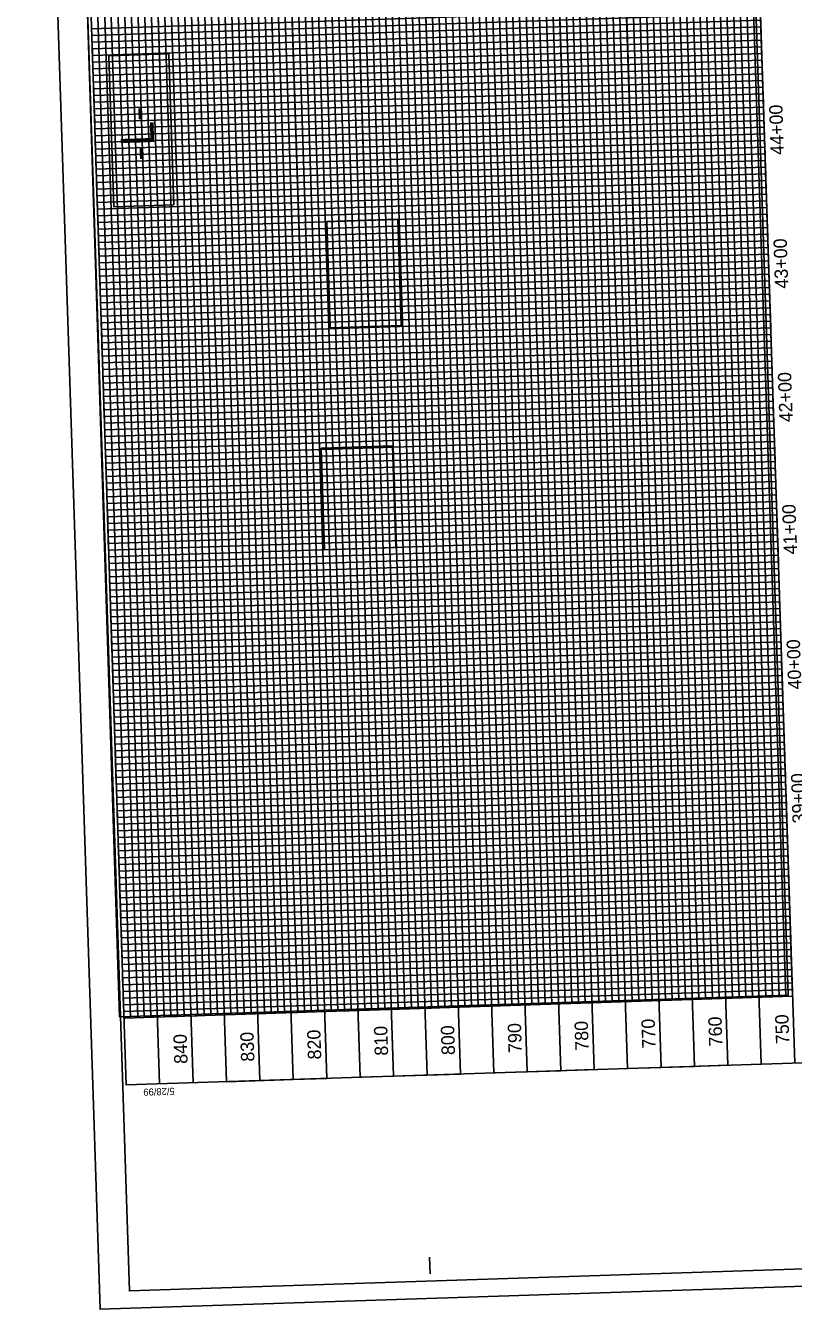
# Model space of a CAD drawing. Extents: x 1627318 to 1628473, y 762308 to 764226.
# Drawn here: x 1627318 to 1627891, y 762308 to 763268 of the extents above; entities that cross this region are included whole.
import ezdxf

# ---------------------------------------------------------------- set-up
doc = ezdxf.new("R2010")
doc.units = 0
for name, color, linetype in [('Exist Vertical Profile Horizontal Axis Label Major', 7, 'Continuous'), ('Exist Vertical Profile Vertical Axis Label', 7, 'Continuous'), ('Prop Grid Mask', 7, 'Continuous'), ('Sheet Data Field CELL', 7, 'Continuous'), ('Sheet DOT Grid CELL', 7, 'Continuous'), ('Sheet Layout Profile Border Port 1', 7, 'Continuous'), ('Sheet Plot Border Inside CELL', 7, 'Continuous'), ('Sheet Plot Border Outside CELL', 7, 'Continuous'), ('Sheet Profile CELL', 7, 'Continuous'), ('Sheet Profile Grid Major CELL', 7, 'Continuous'), ('Sheet Profile Grid Middle CELL', 7, 'Continuous'), ('Sheet Profile Grid Minor CELL', 7, 'Continuous')]:
    doc.layers.add(name, color=color, linetype=linetype)

msp = doc.modelspace()

# ---------------------------------------------------------------- linework, layer by layer
at = {"layer": 'Prop Grid Mask'}
for points in [[(1627428.21, 763133.99), (1627424.52, 763247.02), (1627379.8, 763245.55), (1627383.49, 763132.53)], [(1627545.26, 763042.21), (1627542.66, 763121.69), (1627595.71, 763123.43), (1627598.31, 763043.95)], [(1627540.99, 762876.11), (1627538.5, 762952.17), (1627591.68, 762953.91), (1627594.17, 762877.85)]]:
    msp.add_lwpolyline(points, close=True, dxfattribs=at)
at = {"layer": 'Sheet DOT Grid CELL'}
for p, q in [((1627593.48, 763983.54), (1627642.52, 762484.34)), ((1627643.46, 763985.17), (1627692.5, 762485.97)), ((1627693.43, 763986.81), (1627742.47, 762487.61)), ((1627743.4, 763988.44), (1627792.44, 762489.24)), ((1627793.38, 763990.08), (1627842.42, 762490.88)), ((1627500.08, 763780.37), (1627542.58, 762481.07)), ((1627550.05, 763781.96), (1627592.55, 762482.7)), ((1627400.13, 763777.06), (1627442.63, 762477.8)), ((1627450.11, 763778.69), (1627492.6, 762479.43)), ((1627867.87, 763242.11), (1627368.14, 763225.76)), ((1627869.51, 763192.14), (1627369.77, 763175.79)), ((1627871.14, 763142.16), (1627371.41, 763125.82)), ((1627872.77, 763092.19), (1627373.04, 763075.84)), ((1627874.41, 763042.22), (1627374.68, 763025.87)), ((1627876.04, 762992.24), (1627376.31, 762975.9)), ((1627877.68, 762942.27), (1627377.95, 762925.93)), ((1627879.31, 762892.3), (1627379.58, 762875.95)), ((1627880.95, 762842.32), (1627381.21, 762825.98)), ((1627882.58, 762792.35), (1627382.85, 762776.01)), ((1627884.22, 762742.38), (1627384.48, 762726.03)), ((1627885.85, 762692.4), (1627386.12, 762676.06)), ((1627887.49, 762642.43), (1627387.75, 762626.09)), ((1627889.12, 762592.46), (1627389.39, 762576.11)), ((1627890.76, 762542.49), (1627391.02, 762526.14))]:
    msp.add_line(p, q, dxfattribs=at)
at = {"layer": 'Sheet Layout Profile Border Port 1'}
msp.add_lwpolyline([(1627387.69, 762527.01), (1627887.42, 762543.36), (1627841.65, 763942.61), (1627566.8, 763933.62), (1627571.7, 763783.65), (1627346.82, 763776.3), (1627347.71, 763777.21)], close=True, dxfattribs=at)
msp.add_lwpolyline([(1627551.99, 762531.4), (1627890.76, 762542.49), (1627844.99, 763941.74), (1627570.13, 763932.75)], dxfattribs=at)
at = {"layer": 'Sheet Plot Border Inside CELL'}
msp.add_lwpolyline([(1628449.68, 762356.66), (1628395.2, 764022.27), (1627340.66, 763987.77), (1627395.14, 762322.16)], close=True, dxfattribs=at)
at = {"layer": 'Sheet Plot Border Outside CELL'}
msp.add_lwpolyline([(1628472.54, 762344.4), (1628416.96, 764043.49), (1627317.55, 764007.53), (1627373.13, 762308.44)], close=True, dxfattribs=at)
at = {"layer": 'Sheet Profile CELL'}
for p, q in [((1627892.39, 762492.51), (1627843.35, 763991.71)), ((1627619.89, 762335.02), (1627619.48, 762347.51))]:
    msp.add_line(p, q, dxfattribs=at)
msp.add_lwpolyline([(1627343.62, 763975.36), (1627392.66, 762476.17), (1628442.1, 762510.49), (1628393.06, 764009.69)], close=True, dxfattribs=at)
at = {"layer": 'Sheet Profile Grid Major CELL'}
for points in [[(1627550.05, 763782.01), (1627592.55, 762482.7), (1627642.52, 762484.34), (1627593.48, 763983.54)], [(1627643.46, 763985.17), (1627692.5, 762485.97), (1627742.47, 762487.61), (1627693.43, 763986.81)], [(1627743.4, 763988.44), (1627792.44, 762489.24), (1627792.44, 762489.24), (1627842.42, 762490.88), (1627793.38, 763990.08)], [(1627450.1, 763778.74), (1627492.6, 762479.43), (1627542.58, 762481.07), (1627500.08, 763780.37)], [(1627442.63, 762477.8), (1627400.13, 763777.11)], [(1627391.02, 762526.14), (1627890.76, 762542.49), (1627889.12, 762592.46), (1627389.39, 762576.11), (1627387.75, 762626.09), (1627887.49, 762642.43), (1627885.85, 762692.4), (1627386.12, 762676.06), (1627384.48, 762726.03), (1627884.22, 762742.38), (1627882.58, 762792.35), (1627382.85, 762776.01), (1627381.21, 762825.98), (1627880.95, 762842.32), (1627879.31, 762892.3), (1627379.58, 762875.95), (1627377.95, 762925.93), (1627877.68, 762942.27), (1627876.04, 762992.24), (1627376.31, 762975.9), (1627374.68, 763025.87), (1627874.41, 763042.22), (1627872.77, 763092.19), (1627373.04, 763075.84), (1627371.41, 763125.82), (1627871.14, 763142.16), (1627869.51, 763192.14), (1627369.77, 763175.79), (1627368.14, 763225.76), (1627867.87, 763242.11), (1627866.24, 763292.08)]]:
    msp.add_lwpolyline(points, dxfattribs=at)
at = {"layer": 'Sheet Profile Grid Middle CELL'}
msp.add_line((1627417.64, 762476.98), (1627375.15, 763776.24), dxfattribs=at)
for points in [[(1627818.36, 763990.89), (1627867.4, 762491.69)], [(1627618.47, 763984.35), (1627667.51, 762485.16), (1627717.48, 762486.79), (1627668.44, 763985.99)], [(1627718.42, 763987.62), (1627767.46, 762488.43), (1627817.43, 762490.06), (1627768.39, 763989.26)], [(1627525.07, 763781.14), (1627567.56, 762481.89), (1627617.54, 762483.52), (1627574.22, 763807.81)], [(1627425.12, 763777.92), (1627467.62, 762478.62), (1627517.59, 762480.25), (1627475.09, 763779.56)], [(1627390.21, 762551.13), (1627889.94, 762567.47), (1627888.3, 762617.44), (1627388.57, 762601.1), (1627386.94, 762651.07), (1627886.67, 762667.42), (1627885.03, 762717.39), (1627385.3, 762701.05), (1627383.67, 762751.02), (1627883.4, 762767.36), (1627881.76, 762817.34), (1627382.03, 762800.99), (1627380.4, 762850.97), (1627880.13, 762867.31), (1627878.5, 762917.28), (1627378.76, 762900.94), (1627377.13, 762950.91), (1627876.86, 762967.26), (1627875.23, 763017.23), (1627375.49, 763000.88), (1627373.86, 763050.86), (1627873.59, 763067.2), (1627871.96, 763117.18), (1627871.96, 763117.18), (1627372.22, 763100.83), (1627370.59, 763150.8), (1627870.32, 763167.15), (1627868.69, 763217.12), (1627368.96, 763200.78), (1627367.32, 763250.75), (1627867.05, 763267.1), (1627865.42, 763317.07)]]:
    msp.add_lwpolyline(points, dxfattribs=at)
at = {"layer": 'Sheet Profile Grid Minor CELL'}
for p, q in [((1627580.13, 763933.07), (1627625.9, 762533.82)), ((1627630.89, 762533.99), (1627585.12, 763933.24)), ((1627590.12, 763933.4), (1627635.89, 762534.15)), ((1627645.89, 762534.48), (1627600.12, 763933.73)), ((1627605.11, 763933.89), (1627650.88, 762534.64)), ((1627655.88, 762534.8), (1627610.11, 763934.05)), ((1627615.11, 763934.22), (1627660.88, 762534.97)), ((1627670.87, 762535.29), (1627625.1, 763934.54)), ((1627630.1, 763934.71), (1627675.87, 762535.46)), ((1627680.87, 762535.62), (1627635.1, 763934.87)), ((1627640.1, 763935.03), (1627685.86, 762535.78)), ((1627695.86, 762536.11), (1627650.09, 763935.36)), ((1627655.09, 763935.53), (1627700.86, 762536.27)), ((1627705.85, 762536.44), (1627660.08, 763935.69)), ((1627665.08, 763935.85), (1627710.85, 762536.6)), ((1627720.85, 762536.93), (1627675.08, 763936.18)), ((1627680.07, 763936.34), (1627725.84, 762537.09)), ((1627730.84, 762537.25), (1627685.07, 763936.51)), ((1627690.07, 763936.67), (1627735.84, 762537.42)), ((1627745.83, 762537.74), (1627700.06, 763937)), ((1627705.06, 763937.16), (1627750.83, 762537.91)), ((1627755.83, 762538.07), (1627710.06, 763937.32)), ((1627715.06, 763937.49), (1627760.82, 762538.24)), ((1627770.82, 762538.56), (1627725.05, 763937.81)), ((1627730.05, 763937.98), (1627775.82, 762538.73)), ((1627735.04, 763938.14), (1627780.81, 762538.89)), ((1627740.04, 763938.3), (1627785.81, 762539.05)), ((1627795.81, 762539.38), (1627750.04, 763938.63)), ((1627755.03, 763938.79), (1627800.8, 762539.54)), ((1627805.8, 762539.71), (1627760.03, 763938.96)), ((1627765.03, 763939.12), (1627810.8, 762539.87)), ((1627820.79, 762540.2), (1627775.02, 763939.45)), ((1627780.02, 763939.61), (1627825.79, 762540.36)), ((1627830.79, 762540.52), (1627785.02, 763939.78)), ((1627790.02, 763939.94), (1627835.78, 762540.69)), ((1627845.78, 762541.01), (1627800.01, 763940.27)), ((1627805.01, 763940.43), (1627850.78, 762541.18)), ((1627855.77, 762541.34), (1627810, 763940.59)), ((1627815, 763940.76), (1627860.77, 762541.5)), ((1627870.77, 762541.83), (1627825, 763941.08)), ((1627829.99, 763941.25), (1627875.76, 762541.99)), ((1627880.76, 762542.16), (1627834.99, 763941.41)), ((1627485.09, 763779.83), (1627525.95, 762530.55)), ((1627490.08, 763780.05), (1627530.95, 762530.72)), ((1627495.08, 763780.21), (1627535.94, 762530.88)), ((1627545.94, 762531.21), (1627505.07, 763780.54)), ((1627510.07, 763780.7), (1627550.94, 762531.37)), ((1627555.93, 762531.53), (1627515.07, 763780.81)), ((1627535.06, 763781.47), (1627575.92, 762532.19)), ((1627580.92, 762532.35), (1627540.06, 763781.63)), ((1627560.05, 763782.29), (1627600.91, 762533)), ((1627605.91, 762533.17), (1627565.04, 763782.45)), ((1627396.02, 762526.3), (1627355.15, 763775.63)), ((1627360.15, 763775.8), (1627401.37, 762526.48)), ((1627406.01, 762526.63), (1627365.15, 763775.96)), ((1627401.02, 762526.47), (1627401.02, 762526.47))]:
    msp.add_line(p, q, dxfattribs=at)
for points in [[(1627570.04, 763782.61), (1627610.9, 762533.33), (1627620.9, 762533.66), (1627575.13, 763932.91)], [(1627839.99, 763941.57), (1627885.76, 762542.32)], [(1627460.2, 763779.07), (1627501.06, 762529.84), (1627505.96, 762530), (1627465.1, 763779.23)], [(1627470.09, 763779.39), (1627510.96, 762530.06), (1627520.95, 762530.39), (1627480.09, 763779.72)], [(1627520.07, 763780.98), (1627560.93, 762531.7), (1627570.93, 762532.02), (1627530.06, 763781.31)], [(1627545.05, 763781.8), (1627585.92, 762532.51), (1627595.91, 762532.84), (1627555.05, 763782.12)], [(1627370.15, 763776.12), (1627411.01, 762526.79), (1627421.01, 762527.12), (1627380.14, 763776.45)], [(1627385.14, 763776.56), (1627426, 762527.28), (1627431, 762527.45), (1627390.14, 763776.78)], [(1627395.13, 763776.94), (1627436, 762527.61), (1627445.99, 762527.94), (1627405.13, 763777.27)], [(1627410.12, 763777.43), (1627450.99, 762528.1), (1627455.99, 762528.26), (1627415.12, 763777.6)], [(1627420.12, 763777.76), (1627460.99, 762528.43), (1627470.98, 762528.75), (1627430.11, 763778.09)], [(1627435.11, 763778.25), (1627475.98, 762528.92), (1627480.97, 762529.08), (1627440.11, 763778.41)], [(1627445.11, 763778.58), (1627485.97, 762529.24), (1627495.97, 762529.57), (1627455.1, 763778.9)], [(1627866.73, 763277.09), (1627366.99, 763260.75), (1627366.83, 763265.74), (1627866.56, 763282.09)], [(1627373.7, 763055.86), (1627873.43, 763072.2), (1627873.26, 763077.2), (1627373.53, 763060.85), (1627373.37, 763065.85), (1627873.1, 763082.2), (1627872.94, 763087.19), (1627373.21, 763070.85), (1627372.88, 763080.84), (1627872.61, 763097.19), (1627872.45, 763102.19), (1627372.71, 763085.84), (1627372.55, 763090.84), (1627872.28, 763107.18), (1627872.12, 763112.18), (1627372.39, 763095.83), (1627372.06, 763105.83), (1627871.79, 763122.18), (1627871.63, 763127.17), (1627371.9, 763110.83), (1627371.73, 763115.82), (1627871.47, 763132.17), (1627871.3, 763137.17), (1627371.57, 763120.82), (1627371.24, 763130.82), (1627870.98, 763147.16), (1627870.81, 763152.16), (1627371.08, 763135.81), (1627370.92, 763140.81), (1627870.65, 763157.16), (1627870.49, 763162.15), (1627370.75, 763145.81), (1627370.43, 763155.8), (1627870.16, 763172.15), (1627870, 763177.15), (1627370.26, 763160.8), (1627370.1, 763165.8), (1627869.83, 763182.14), (1627869.67, 763187.14), (1627369.94, 763170.79), (1627369.61, 763180.79), (1627869.34, 763197.13), (1627869.34, 763197.13), (1627869.18, 763202.13), (1627369.45, 763185.79), (1627369.28, 763190.78), (1627869.01, 763207.13), (1627868.85, 763212.13), (1627369.12, 763195.78), (1627368.79, 763205.78), (1627868.52, 763222.12), (1627868.36, 763227.12), (1627368.63, 763210.77), (1627368.46, 763215.77), (1627868.2, 763232.12), (1627868.03, 763237.11), (1627368.3, 763220.77), (1627367.97, 763230.76), (1627867.71, 763247.11), (1627867.54, 763252.11), (1627367.81, 763235.76), (1627367.65, 763240.76), (1627867.38, 763257.1), (1627867.22, 763262.1), (1627367.48, 763245.75), (1627367.16, 763255.75), (1627866.89, 763272.09)], [(1627883.73, 762757.37), (1627883.56, 762762.37), (1627383.83, 762746.02), (1627383.5, 762756.02), (1627883.24, 762772.36), (1627883.07, 762777.36), (1627383.34, 762761.01), (1627383.18, 762766.01), (1627882.91, 762782.36), (1627882.75, 762787.35), (1627383.01, 762771.01), (1627382.69, 762781), (1627882.42, 762797.35), (1627882.26, 762802.35), (1627382.52, 762786), (1627382.36, 762791), (1627882.09, 762807.34), (1627881.93, 762812.34), (1627382.2, 762795.99), (1627381.87, 762805.99), (1627881.6, 762822.34), (1627881.44, 762827.33), (1627381.71, 762810.99), (1627381.54, 762815.98), (1627881.27, 762832.33), (1627881.11, 762837.33), (1627381.38, 762820.98), (1627381.05, 762830.98), (1627880.78, 762847.32), (1627880.62, 762852.32), (1627380.89, 762835.97), (1627380.72, 762840.97), (1627880.46, 762857.32), (1627880.29, 762862.31), (1627380.56, 762845.97), (1627380.23, 762855.96), (1627879.97, 762872.31), (1627879.8, 762877.31), (1627380.07, 762860.96), (1627379.91, 762865.96), (1627879.64, 762882.3), (1627879.48, 762887.3), (1627379.74, 762870.95), (1627379.42, 762880.95), (1627879.15, 762897.3), (1627878.99, 762902.29), (1627379.25, 762885.95), (1627379.09, 762890.94), (1627878.82, 762907.29), (1627878.66, 762912.29), (1627378.93, 762895.94), (1627378.6, 762905.94), (1627878.33, 762922.28), (1627878.17, 762927.28), (1627378.44, 762910.93), (1627378.27, 762915.93), (1627878.01, 762932.28), (1627877.84, 762937.27), (1627378.11, 762920.93), (1627377.78, 762930.92), (1627877.51, 762947.27), (1627877.35, 762952.27), (1627377.62, 762935.92), (1627377.46, 762940.92), (1627877.19, 762957.26), (1627877.02, 762962.26), (1627377.29, 762945.91), (1627376.96, 762955.91), (1627876.7, 762972.26), (1627876.53, 762977.25), (1627376.8, 762960.91), (1627376.64, 762965.9), (1627876.37, 762982.25), (1627876.21, 762987.25), (1627376.47, 762970.9), (1627376.15, 762980.9), (1627875.88, 762997.24), (1627875.72, 763002.24), (1627375.98, 762985.89), (1627375.82, 762990.89), (1627875.55, 763007.24), (1627875.39, 763012.23), (1627375.66, 762995.89), (1627375.33, 763005.88), (1627875.06, 763022.23), (1627874.9, 763027.23), (1627375.17, 763010.88), (1627375, 763015.88), (1627874.74, 763032.22), (1627874.57, 763037.22), (1627374.84, 763020.87), (1627374.51, 763030.87), (1627874.25, 763047.22), (1627874.08, 763052.21), (1627374.35, 763035.87), (1627374.19, 763040.86), (1627873.92, 763057.21), (1627873.76, 763062.21), (1627374.02, 763045.86), (1627373.7, 763055.86)], [(1627390.86, 762531.14), (1627890.59, 762547.48), (1627890.43, 762552.48), (1627390.7, 762536.13), (1627390.53, 762541.13), (1627890.26, 762557.48), (1627890.1, 762562.47), (1627390.37, 762546.13), (1627390.04, 762556.12), (1627889.77, 762572.47), (1627889.61, 762577.47), (1627389.88, 762561.12), (1627389.71, 762566.12), (1627889.45, 762582.46), (1627889.28, 762587.46), (1627888.96, 762597.46), (1627888.79, 762602.45), (1627389.06, 762586.11), (1627388.9, 762591.1), (1627888.63, 762607.45), (1627888.47, 762612.45), (1627388.73, 762596.1), (1627388.41, 762606.1), (1627888.14, 762622.44), (1627887.98, 762627.44), (1627388.24, 762611.09), (1627388.08, 762616.09), (1627887.81, 762632.44), (1627887.65, 762637.43), (1627387.92, 762621.09), (1627387.59, 762631.08), (1627887.32, 762647.43), (1627887.16, 762652.43), (1627387.43, 762636.08), (1627387.26, 762641.08), (1627887, 762657.42), (1627886.83, 762662.42), (1627387.1, 762646.07), (1627386.77, 762656.07), (1627886.51, 762672.42), (1627886.34, 762677.41), (1627386.61, 762661.07), (1627386.45, 762666.06), (1627886.18, 762682.41), (1627886.01, 762687.41), (1627386.28, 762671.06), (1627385.96, 762681.06), (1627885.69, 762697.4), (1627885.52, 762702.4), (1627385.79, 762686.05), (1627385.63, 762691.05), (1627885.36, 762707.4), (1627885.2, 762712.39), (1627385.46, 762696.05), (1627385.14, 762706.04), (1627884.87, 762722.39), (1627884.71, 762727.39), (1627384.97, 762711.04), (1627384.81, 762716.04), (1627884.54, 762732.38), (1627884.38, 762737.38), (1627384.65, 762721.03), (1627384.32, 762731.03), (1627884.05, 762747.38), (1627883.89, 762752.37), (1627384.16, 762736.03), (1627383.99, 762741.02), (1627883.73, 762757.37)], [(1627889.28, 762587.46), (1627389.55, 762571.11), (1627389.22, 762581.11), (1627888.96, 762597.46)]]:
    msp.add_lwpolyline(points, dxfattribs=at)

# ---------------------------------------------------------------- texts
at = {"layer": 'Exist Vertical Profile Horizontal Axis Label Major'}
for s, p in [('44+00', (1627884.38, 763171.6)), ('43+00', (1627887.65, 763071.58)), ('42+00', (1627890.92, 762971.68)), ('41+00', (1627894.15, 762872.96)), ('40+00', (1627897.45, 762771.93)), ('39+00', (1627900.73, 762671.86))]:
    msp.add_text(s, height=10, rotation=91.87347, dxfattribs=at).set_placement(p)
at = {"layer": 'Exist Vertical Profile Vertical Axis Label'}
for s, p in [('780', (1627738.45, 762501.9)), ('770', (1627788.42, 762503.53)), ('760', (1627838.39, 762505.17)), ('750', (1627888.37, 762506.8)), ('840', (1627438.61, 762492.09)), ('830', (1627488.58, 762493.73)), ('820', (1627538.55, 762495.36)), ('810', (1627588.49, 762498.19)), ('800', (1627638.5, 762498.63)), ('790', (1627688.47, 762500.27))]:
    msp.add_text(s, height=10, rotation=91.87347, dxfattribs=at).set_placement(p)
at = {"layer": 'Sheet Data Field CELL'}
msp.add_text('-L-', height=25, rotation=91.87347, dxfattribs=at).set_placement((1627414.07, 763167.16))
at = {"layer": 'Sheet Profile CELL'}
msp.add_text('5/28/99', height=5.25, rotation=181.87347, dxfattribs=at).set_placement((1627428.83, 762474.11))

doc.saveas('drawing.dxf')
